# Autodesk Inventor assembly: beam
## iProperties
Shininess: 64.0
Length Units: 11269
Angle Units: 11279
Time Units: 11290
Mass Units: 11283
Length Display Precision: 3
Angle Display Precision: 2
Compacted: True
Created: 2004-07
Part Number: beam
Document SubType Name: Assembly
Designer: Peter
Manufacturer: Standard
Standards Organization: Custom
Density: 0.0
Volumn: 0.0
Area: 0.0
PropertySet Name: Model Information
Control State: 0
Master: False
Checked Out: False
Author: Peter
